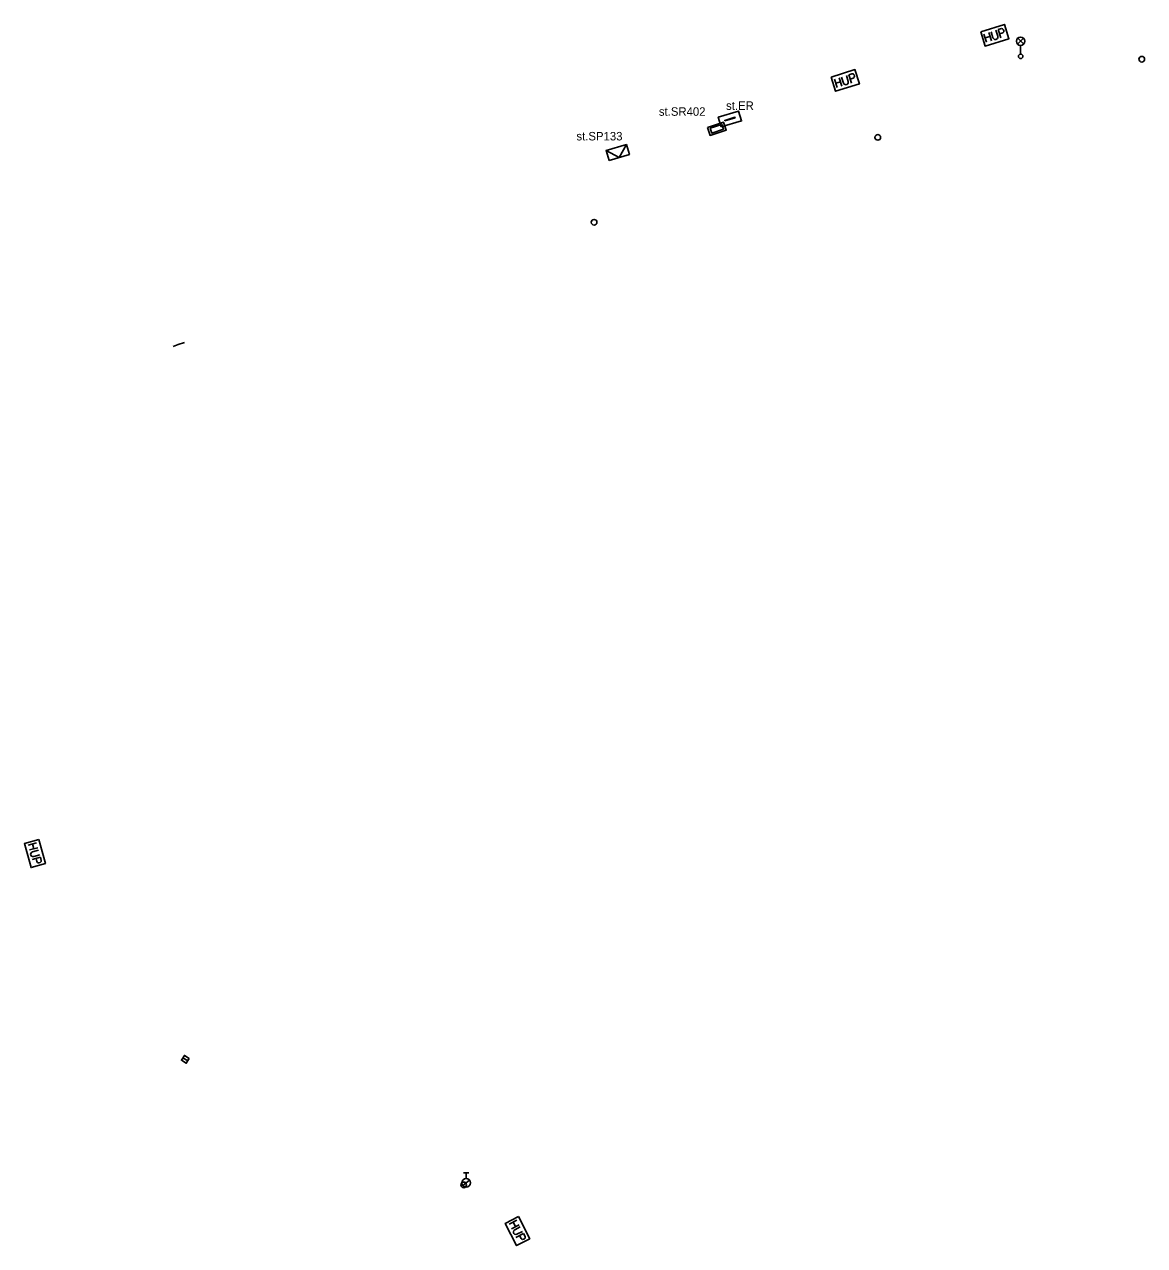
# Model space of a CAD drawing. Extents: x -762500 to -761250, y -1152983 to -1152297.
# Drawn here: x -761372.4 to -761273.3, y -1152404.9 to -1152296.9 of the extents above; entities that cross this region are included whole.
import ezdxf

# ---------------------------------------------------------------- set-up
doc = ezdxf.new("R2010")
doc.units = 0
for name, color, linetype in [('Vrstva 1', 7, 'Continuous'), ('Vrstva 11', 7, 'Continuous'), ('Vrstva 2', 7, 'Continuous'), ('Vrstva 5', 7, 'Continuous'), ('Vrstva 9', 7, 'Continuous')]:
    doc.layers.add(name, color=color, linetype=linetype)

msp = doc.modelspace()

# ---------------------------------------------------------------- linework, layer by layer
at = {"layer": 'Vrstva 1'}
for points in [[(-761310.748, -1152305.989), (-761308.952, -1152305.451), (-761309.21, -1152304.589), (-761311.006, -1152305.126)], [(-761311.964, -1152306.027), (-761310.537, -1152305.566), (-761310.306, -1152306.279), (-761311.734, -1152306.741)], [(-761311.728, -1152306.108), (-761310.681, -1152305.77), (-761310.543, -1152306.198), (-761311.589, -1152306.536)], [(-761310.423, -1152305.441), (-761309.524, -1152305.173), (-761309.535, -1152305.137), (-761310.433, -1152305.405)], [(-761320.67, -1152308.943), (-761318.87, -1152308.417), (-761319.123, -1152307.553), (-761320.922, -1152308.079)]]:
    msp.add_lwpolyline(points, close=True, dxfattribs=at)
msp.add_lwpolyline([(-761320.922, -1152308.079), (-761319.77, -1152308.68), (-761319.123, -1152307.553)], dxfattribs=at)
at = {"layer": 'Vrstva 11'}
msp.add_lwpolyline([(-761358.22, -1152325.05), (-761358.76, -1152325.22), (-761359.2, -1152325.4)], dxfattribs=at)
at = {"layer": 'Vrstva 5'}
for points in [[(-761287.801, -1152297.574), (-761285.699, -1152296.924), (-761285.309, -1152298.185), (-761287.411, -1152298.835), (-761287.801, -1152297.574)], [(-761286.879, -1152297.577), (-761286.716, -1152298.104), (-761286.654, -1152298.198), (-761286.568, -1152298.248), (-761286.468, -1152298.256), (-761286.408, -1152298.237), (-761286.33, -1152298.174), (-761286.291, -1152298.086), (-761286.294, -1152297.973), (-761286.457, -1152297.446)], [(-761286.249, -1152297.382), (-761285.975, -1152297.297), (-761285.877, -1152297.305), (-761285.834, -1152297.33), (-761285.783, -1152297.39), (-761285.751, -1152297.495), (-761285.759, -1152297.573), (-761285.78, -1152297.617), (-761285.857, -1152297.679), (-761286.13, -1152297.764)], [(-761286.021, -1152298.117), (-761286.249, -1152297.382)], [(-761287.51, -1152297.772), (-761287.282, -1152298.507)], [(-761287.402, -1152298.119), (-761286.98, -1152297.988)], [(-761286.86, -1152298.377), (-761287.087, -1152297.641)], [(-761301.021, -1152301.574), (-761298.919, -1152300.924), (-761298.529, -1152302.185), (-761300.631, -1152302.835), (-761301.021, -1152301.574)], [(-761300.73, -1152301.772), (-761300.502, -1152302.507)], [(-761300.08, -1152302.377), (-761300.307, -1152301.641)], [(-761300.099, -1152301.577), (-761299.936, -1152302.104), (-761299.874, -1152302.198), (-761299.788, -1152302.248), (-761299.688, -1152302.256), (-761299.628, -1152302.237), (-761299.55, -1152302.174), (-761299.511, -1152302.086), (-761299.514, -1152301.973), (-761299.677, -1152301.446)], [(-761299.469, -1152301.382), (-761299.195, -1152301.297), (-761299.097, -1152301.305), (-761299.054, -1152301.33), (-761299.003, -1152301.39), (-761298.971, -1152301.495), (-761298.979, -1152301.573), (-761299, -1152301.617), (-761299.077, -1152301.679), (-761299.35, -1152301.764)], [(-761299.241, -1152302.117), (-761299.469, -1152301.382)], [(-761300.622, -1152302.119), (-761300.2, -1152301.988)]]:
    msp.add_lwpolyline(points, dxfattribs=at)
at = {"layer": 'Vrstva 9'}
for p, q in [((-761284.534, -1152298.678), (-761284.006, -1152298.15)), ((-761283.998, -1152298.675), (-761284.526, -1152298.146)), ((-761284.27, -1152298.79), (-761284.27, -1152299.54)), ((-761357.918, -1152388.553), (-761358.342, -1152388.287)), ((-761333.55, -1152398.465), (-761333.05, -1152398.465)), ((-761333.3, -1152398.965), (-761333.3, -1152398.465)), ((-761333.594, -1152399.571), (-761333.004, -1152399.108))]:
    msp.add_line(p, q, dxfattribs=at)
for points in [[(-761371.091, -1152368.998), (-761370.505, -1152371.119), (-761371.777, -1152371.47), (-761372.363, -1152369.35), (-761371.091, -1152368.998)], [(-761371.297, -1152369.283), (-761372.039, -1152369.489)], [(-761371.922, -1152369.915), (-761371.179, -1152369.71)], [(-761371.647, -1152369.38), (-761371.529, -1152369.806)], [(-761371.121, -1152369.92), (-761371.653, -1152370.067), (-761371.749, -1152370.125), (-761371.801, -1152370.21), (-761371.812, -1152370.31), (-761371.796, -1152370.371), (-761371.735, -1152370.45), (-761371.648, -1152370.492), (-761371.536, -1152370.493), (-761371.004, -1152370.346)], [(-761371.688, -1152370.761), (-761370.946, -1152370.556)], [(-761370.946, -1152370.556), (-761370.869, -1152370.831), (-761370.881, -1152370.93), (-761370.906, -1152370.971), (-761370.968, -1152371.02), (-761371.074, -1152371.05), (-761371.152, -1152371.039), (-761371.195, -1152371.017), (-761371.255, -1152370.938), (-761371.331, -1152370.662)], [(-761328.675, -1152402.33), (-761327.674, -1152404.289), (-761328.849, -1152404.889), (-761329.851, -1152402.931), (-761328.675, -1152402.33)], [(-761328.82, -1152402.651), (-761329.506, -1152403.001)], [(-761329.304, -1152403.395), (-761328.619, -1152403.044)], [(-761329.143, -1152402.816), (-761328.942, -1152403.21)], [(-761328.52, -1152403.239), (-761329.011, -1152403.49), (-761329.093, -1152403.566), (-761329.127, -1152403.66), (-761329.118, -1152403.76), (-761329.089, -1152403.816), (-761329.014, -1152403.882), (-761328.92, -1152403.905), (-761328.81, -1152403.883), (-761328.318, -1152403.632)], [(-761328.905, -1152404.177), (-761328.219, -1152403.826)], [(-761328.219, -1152403.826), (-761328.089, -1152404.081), (-761328.08, -1152404.18), (-761328.097, -1152404.225), (-761328.147, -1152404.286), (-761328.245, -1152404.336), (-761328.324, -1152404.341), (-761328.37, -1152404.328), (-761328.445, -1152404.263), (-761328.575, -1152404.008)]]:
    msp.add_lwpolyline(points, dxfattribs=at)
msp.add_lwpolyline([(-761357.785, -1152388.34), (-761358.209, -1152388.074), (-761358.475, -1152388.499), (-761358.051, -1152388.765)], close=True, dxfattribs=at)
for centre, radius in [((-761284.27, -1152298.415), 0.375), ((-761284.27, -1152299.74), 0.2), ((-761273.56, -1152300), 0.25), ((-761296.9, -1152306.91), 0.25), ((-761321.99, -1152314.42), 0.25), ((-761333.3, -1152399.34), 0.375), ((-761333.52, -1152399.52), 0.25)]:
    msp.add_circle(centre, radius, dxfattribs=at)

# ---------------------------------------------------------------- texts
at = {"layer": 'Vrstva 2'}
for s, p in [('st.ER', (-761310.32, -1152304.48)), ('st.SR402', (-761316.26, -1152305)), ('st.SP133', (-761323.55, -1152307.18))]:
    msp.add_text(s, height=0.75, dxfattribs=at).set_placement(p)

doc.saveas('drawing.dxf')
